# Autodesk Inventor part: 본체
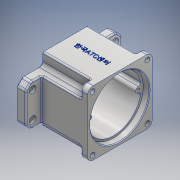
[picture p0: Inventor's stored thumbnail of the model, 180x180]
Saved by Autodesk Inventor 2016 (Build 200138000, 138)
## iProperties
Created: 2017-01
Part Number: 본체
Material: 알루미늄 6061
Document SubType Name: Modeling
Designer: Owner
Density: 2.7 g/cm^3
Appearance: 알루미늄 - 평지
Mass: 877.754 g
Surface Area: 763.669 cm^2
Volume: 325.094 cm^3
Author: Owner
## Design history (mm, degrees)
sketch "스케치4"
  geometry: L1 (70, -30)-(70, 30); L2 (-70, -30)-(-70, 30); L3 (-33, -47)-(33, -47); L4 (33, 47)-(-33, 47); L5 (70, 30)-(33, 30); L6 (-33, -30)-(-70, -30); L7 (-33, 47)-(-33, 30); L8 (-33, -30)-(-33, -47); L9 (-70, 30)-(-33, 30); L10 (33, -30)-(70, -30); L11 (33, -47)-(33, -30); L12 (33, 30)-(33, 47); 5 further points
  constraints: 24 end point, 10 equal length, 4 midpoint, 4 perpendicular, 3 horizontal, 2 collinear, 2 horizontal alignment, 2 vertical alignment
  dimensions: "d6" = 66 distance of L4.start L4.end; "d7" = 60 distance of L1.start L1.end; "d8" = 60 distance of L2.start L2.end; "d9" = 66 distance of L3.start L3.end; "d10" = 94 distance between parallel lines of L3 L4; "d11" = 140 distance between parallel lines of L1 L2
extrude "돌출2" new body sketch "스케치4" distance "d12" = 13; taper "d13" = 0 deg
sketch "스케치6"
  geometry: L1 (-33, 47)-(33, 47); L2 (33, 47)-(33, -47); L3 (33, -47)-(-33, -47); L4 (-33, -47)-(-33, 47); L5 (-33, 47)-(33, -47); L6 (33, 47)-(-33, -47); 1 further point
  constraints: 12 end point, 2 midpoint, 2 parallel, 1 horizontal, 1 perpendicular
extrude "돌출3" join sketch "스케치6" distance "d16" = 80; taper "d17" = 0 deg
sketch "스케치7"
  geometry: C1 r 27.5 at (11, 0); 2 further points
  constraints: 1 centre point, 1 coincident, 1 horizontal alignment
  dimensions: "d18" = 11 distance of point (11, 0) point (0, 0); "d19" = 55 diameter of C1
extrude "돌출4" join sketch "스케치7" distance "d20" = 7; taper "d21" = 0 deg
hole "구멍1" diameter "d24" = 32; stored, may be unused: countersink angle "d28" = 90 deg, drill point angle "d30" = 0 deg; dims "d25" = 6, "d26" = 4, "d27" = 2, "d29" = 8, "d31" = 10, "d32" = 10
hole "구멍2" diameter "d35" = 25; stored, may be unused: countersink angle "d39" = 90 deg, drill point angle "d41" = 0 deg; dims "d36" = 6, "d37" = 4, "d38" = 2, "d40" = 5, "d42" = 10, "d43" = 10
sketch "스케치8"
  geometry: L1 (-47, -47)-(47, -47); L2 (47, -47)-(47, 47); L3 (47, 47)-(-47, 47); L4 (-47, 47)-(-47, -47); L5 (-47, -47)-(47, 47); L6 (47, -47)-(-47, 47); 1 further point
  constraints: 12 end point, 2 midpoint, 2 parallel, 1 horizontal, 1 perpendicular
  dimensions: "d44" = 94 distance of L3.end L1.start; "d45" = 94 distance of L2.end L3.end
extrude "돌출5" join sketch "스케치8" distance "d46" = 10; taper "d47" = 0 deg
sketch "스케치9"
  geometry: L1 (30, 33)-(30, 70) reference; L2 (-30, -47)-(30, -47); L3 (30, -47)-(30, 47); L4 (30, 47)-(-30, 47); L5 (-30, 47)-(-30, -47); L6 (-30, -47)-(30, 47); L7 (30, -47)-(-30, 47); 1 further point
  constraints: 12 end point, 2 midpoint, 2 parallel, 1 horizontal, 1 perpendicular, 1 point on line
  dimensions: "d48" = 94 distance of L4.end L2.start
extrude "돌출6" join sketch "스케치9" stored distance "d49" = 10; taper "d50" = 0 deg
sketch "스케치10"
  geometry: 2 further points
  constraints: 1 coincident
hole "구멍3" sketch "스케치10" at (0, 0) diameter "d51" = 80; stored, may be unused: countersink angle "d55" = 90 deg, drill point angle "d57" = 0 deg; dims "d52" = 6, "d53" = 4, "d54" = 2, "d56" = 71
sketch "스케치11"
  geometry: A1 r 21 centre (-11, 0) between (7.984, 8.978) and (7.984, -8.978); A2 r 15 centre (20, 0) between (7.984, -8.978) and (7.984, 8.978); 3 further points
  constraints: 4 point on circle, 2 centre point, 2 coincident, 1 horizontal alignment
  dimensions: "d58" = 42 diameter of A1; "d71" = 20 distance of point (20, 0) point (0, 0); "d72" = 30 diameter of A2
extrude "돌출7" join sketch "스케치11" distance "d59" = 7; taper "d60" = 0 deg
hole "구멍4" diameter "d63" = 35; stored, may be unused: countersink angle "d67" = 90 deg, drill point angle "d69" = 0 deg; dims "d61" = 10, "d62" = 10, "d64" = 6, "d65" = 4, "d66" = 2, "d68" = 10
fillet "모깎기1" dims "d70" = 0.3
hole "구멍5" diameter "d75" = 22; stored, may be unused: countersink angle "d79" = 90 deg, drill point angle "d81" = 0 deg; dims "d73" = 10, "d74" = 10, "d76" = 6, "d77" = 4, "d78" = 2, "d80" = 7
hole "구멍6" diameter "d84" = 19; stored, may be unused: countersink angle "d88" = 90 deg, drill point angle "d90" = 0 deg; dims "d82" = 10, "d83" = 10, "d85" = 6, "d86" = 4, "d87" = 2, "d89" = 1
fillet "모깎기2" dims "d91" = 0.3
fillet "모깎기3" dims "d92" = 2
hole "구멍7" diameter "d95" = 86; stored, may be unused: countersink angle "d99" = 90 deg, drill point angle "d101" = 0 deg; dims "d93" = 10, "d94" = 10, "d96" = 6, "d97" = 4, "d98" = 2, "d100" = 9
fillet "모깎기4" dims "d102" = 0.3
chamfer "모따기1" distance "d103" = 1; stored, may be unused: second distance "d104" = 2, angle "d105" = 45 deg
sketch "스케치12"
  geometry: C1 r 43 at (0, 0); A1 r 36 centre (0, 0) between (0, 36) and (0, -36); A2 r 4 centre (0, 36) between (-3.997, 35.852) and (3.997, 35.852); A3 r 4 centre (0, -36) between (3.997, -35.852) and (-3.997, -35.852); A4 r 3.5 centre (-7.495, 35.722) between (-3.995, 35.778) and (-8.214, 39.148); A5 r 3.5 centre (7.495, 35.722) between (8.214, 39.148) and (3.995, 35.778); A6 r 3.5 centre (7.495, -35.722) between (3.995, -35.778) and (8.214, -39.148); A7 r 40 centre (0, 0) between (-8.214, 39.148) and (-8.214, -39.148); A8 r 40 centre (0, 0) between (8.214, -39.148) and (8.214, 39.148); A9 r 3.5 centre (-7.495, -35.722) between (-8.214, -39.148) and (-3.995, -35.778); 1 further point
  constraints: 26 point on circle, 10 centre point, 5 tangent, 4 vertical alignment, 3 coincident, 1 horizontal alignment
  dimensions: "d106" = 72 diameter of A1; "d107" = 8 diameter of A2; "d108" = 8 diameter of A3; "d111" = 3.5 radius of A4; "d112" = 3.5 radius of A5; "d113" = 3.5 radius of A6; "d114" = 7 diameter of A9; "d115" = 40 radius of A7; "d116" = 40 radius of A8; "d117" = 86 diameter of C1
extrude "돌출8" join sketch "스케치12" distance "d118" = 62; taper "d119" = 0 deg
sketch "스케치13"
  geometry: 2 further points
  dimensions: "d120" = 60 vertical distance of point (0, 0) point (-19, -60); "d121" = 19 horizontal distance of point (0, 0) point (-19, -60)
hole "구멍8" sketch "스케치13" at (-19, -60) diameter "d122" = 4; stored, may be unused: countersink angle "d126" = 90 deg, drill point angle "d128" = 0 deg; dims "d123" = 6, "d124" = 4, "d125" = 2, "d127" = 9
hole "구멍9" diameter "d131" = 10; stored, may be unused: countersink angle "d135" = 90 deg, drill point angle "d137" = 0 deg; dims "d132" = 6, "d133" = 4, "d134" = 2, "d136" = 4, "d138" = 10, "d139" = 10
fillet "모깎기5" dims "d140" = 8
chamfer "모따기2" distance "d141" = 8; stored, may be unused: second distance "d142" = 2, angle "d143" = 45 deg
fillet "모깎기6" dims "d144" = 5
chamfer "모따기3" distance "d145" = 1; stored, may be unused: second distance "d146" = 2, angle "d147" = 45 deg
fillet "모깎기7" dims "d148" = 5
hole "구멍10" diameter "d151" = 3.242; stored, may be unused: countersink angle "d155" = 90 deg, drill point angle "d157" = 118 deg; dims "d152" = 7, "d153" = 4, "d154" = 2, "d156" = 9, "d189" = 10, "d190" = 10
sketch "스케치14"
  geometry: 2 further points
  dimensions: "d160" = 40 horizontal distance of point (0, 0) point (-40, 40); "d161" = 40 horizontal distance of point (0, 0) point (-40, 40)
hole "구멍11" sketch "스케치14" at (-40, 40) diameter "d162" = 7; stored, may be unused: countersink angle "d166" = 90 deg, drill point angle "d168" = 0 deg; dims "d163" = 8, "d164" = 4, "d165" = 2, "d167" = 9
fillet "모깎기8" dims "d172" = 2
fillet "모깎기9" dims "d173" = 3
fillet "모깎기10" dims "d174" = 2
fillet "모깎기11" dims "d175" = 2
fillet "모깎기12" dims "d176" = 2
fillet "모깎기13" dims "d177" = 2
fillet "모깎기14" dims "d178" = 2
fillet "모깎기15" dims "d179" = 2
sketch "스케치15"
  geometry: L1 (-80, 70)-(-80, 8) reference; L2 (0, 78)-(0, 0) reference; 3 further points
  constraints: 1 horizontal alignment, 1 midpoint, 1 other
  dimensions: "d180" = 40 distance from line of L2 point (-40, 39)
feature "엠보싱1" sketch "스케치15" dims "d181" = 0.5, "d182" = 0
sketch "스케치16"
  geometry: L1 (35, 33)-(45, 33) reference; L2 (30, 59.929)-(30, 38) reference; L3 (23.464, 68.536)-(28.536, 63.464) reference; L4 (-19.929, 70)-(19.929, 70) reference; L5 (-28.536, 63.464)-(-23.464, 68.536) reference; L6 (-30, 38)-(-30, 59.929) reference; L7 (-45, 33)-(-35, 33) reference; L8 (-47, -31)-(-47, 31) reference; L9 (-35, -33)-(-45, -33) reference; L10 (-30, -59.929)-(-30, -38) reference; L11 (-23.464, -68.536)-(-28.536, -63.464) reference; L12 (19.929, -70)-(-19.929, -70) reference; L13 (28.536, -63.464)-(23.464, -68.536) reference; L14 (30, -38)-(30, -59.929) reference; L15 (45, -33)-(35, -33) reference; L16 (47, 31)-(47, -31) reference; L17 (45, -32)-(35, -32); L18 (29, -38)-(29, -59.929); L19 (27.828, -62.757)-(22.757, -67.828); L20 (19.929, -69)-(-19.929, -69); L21 (-22.757, -67.828)-(-27.828, -62.757); L22 (-29, -59.929)-(-29, -38); L23 (-35, -32)-(-45, -32); L24 (-46, -31)-(-46, 31); L25 (-45, 32)-(-35, 32); L26 (-29, 38)-(-29, 59.929); L27 (-27.828, 62.757)-(-22.757, 67.828); L28 (-19.929, 69)-(19.929, 69); L29 (22.757, 67.828)-(27.828, 62.757); L30 (29, 59.929)-(29, 38); L31 (35, 32)-(45, 32); L32 (46, 31)-(46, -31); L33 (45, -33)-(35, -33); L34 (30, -38)-(30, -59.929); L35 (28.536, -63.464)-(23.464, -68.536); L36 (19.929, -70)-(-19.929, -70); L37 (-23.464, -68.536)-(-28.536, -63.464); L38 (-30, -59.929)-(-30, -38); L39 (-35, -33)-(-45, -33); L40 (-47, -31)-(-47, 31); L41 (-45, 33)-(-35, 33); L42 (-30, 38)-(-30, 59.929); L43 (-28.536, 63.464)-(-23.464, 68.536); L44 (-19.929, 70)-(19.929, 70); L45 (23.464, 68.536)-(28.536, 63.464); L46 (30, 59.929)-(30, 38); L47 (35, 33)-(45, 33); L48 (47, 31)-(47, -31); C1 r 2 at (-19, 60) reference; C2 r 2 at (-19, -60) reference; C3 r 2 at (19, 60) reference; C4 r 2 at (19, -60) reference; C5 r 27.8 at (11, 0) reference; A1 r 2 centre (45, 31) between (47, 31) and (45, 33) reference; A2 r 5 centre (35, 38) between (30, 38) and (35, 33) reference; A3 r 5 centre (25, 59.929) between (30, 59.929) and (28.536, 63.464) reference; A4 r 5 centre (19.929, 65) between (23.464, 68.536) and (19.929, 70) reference; A5 r 5 centre (-19.929, 65) between (-19.929, 70) and (-23.464, 68.536) reference; A6 r 5 centre (-25, 59.929) between (-28.536, 63.464) and (-30, 59.929) reference; A7 r 5 centre (-35, 38) between (-35, 33) and (-30, 38) reference; A8 r 2 centre (-45, 31) between (-45, 33) and (-47, 31) reference; A9 r 2 centre (-45, -31) between (-47, -31) and (-45, -33) reference; A10 r 5 centre (-35, -38) between (-30, -38) and (-35, -33) reference; A11 r 5 centre (-25, -59.929) between (-30, -59.929) and (-28.536, -63.464) reference; A12 r 5 centre (-19.929, -65) between (-23.464, -68.536) and (-19.929, -70) reference; A13 r 5 centre (19.929, -65) between (19.929, -70) and (23.464, -68.536) reference; A14 r 5 centre (25, -59.929) between (28.536, -63.464) and (30, -59.929) reference; A15 r 5 centre (35, -38) between (35, -33) and (30, -38) reference; A16 r 2 centre (45, -31) between (45, -33) and (47, -31) reference; A17 r 1 centre (45, -31) between (45, -32) and (46, -31); A18 r 6 centre (35, -38) between (35, -32) and (29, -38); A19 r 4 centre (25, -59.929) between (27.828, -62.757) and (29, -59.929); A20 r 4 centre (19.929, -65) between (19.929, -69) and (22.757, -67.828); A21 r 4 centre (-19.929, -65) between (-22.757, -67.828) and (-19.929, -69); A22 r 4 centre (-25, -59.929) between (-29, -59.929) and (-27.828, -62.757); A23 r 6 centre (-35, -38) between (-29, -38) and (-35, -32); A24 r 1 centre (-45, -31) between (-46, -31) and (-45, -32); A25 r 1 centre (-45, 31) between (-45, 32) and (-46, 31); A26 r 6 centre (-35, 38) between (-35, 32) and (-29, 38); A27 r 4 centre (-25, 59.929) between (-27.828, 62.757) and (-29, 59.929); A28 r 4 centre (-19.929, 65) between (-19.929, 69) and (-22.757, 67.828); A29 r 4 centre (19.929, 65) between (22.757, 67.828) and (19.929, 69); A30 r 4 centre (25, 59.929) between (29, 59.929) and (27.828, 62.757); A31 r 6 centre (35, 38) between (29, 38) and (35, 32); A32 r 1 centre (45, 31) between (46, 31) and (45, 32); A33 r 2 centre (45, -31) between (45, -33) and (47, -31); A34 r 5 centre (35, -38) between (35, -33) and (30, -38); A35 r 5 centre (25, -59.929) between (28.536, -63.464) and (30, -59.929); A36 r 5 centre (19.929, -65) between (19.929, -70) and (23.464, -68.536); A37 r 5 centre (-19.929, -65) between (-23.464, -68.536) and (-19.929, -70); A38 r 5 centre (-25, -59.929) between (-30, -59.929) and (-28.536, -63.464); A39 r 5 centre (-35, -38) between (-30, -38) and (-35, -33); A40 r 2 centre (-45, -31) between (-47, -31) and (-45, -33); A41 r 2 centre (-45, 31) between (-45, 33) and (-47, 31); A42 r 5 centre (-35, 38) between (-35, 33) and (-30, 38); A43 r 5 centre (-25, 59.929) between (-28.536, 63.464) and (-30, 59.929); A44 r 5 centre (-19.929, 65) between (-19.929, 70) and (-23.464, 68.536); A45 r 5 centre (19.929, 65) between (23.464, 68.536) and (19.929, 70); A46 r 5 centre (25, 59.929) between (30, 59.929) and (28.536, 63.464); A47 r 5 centre (35, 38) between (30, 38) and (35, 33); A48 r 2 centre (45, 31) between (47, 31) and (45, 33); 1 further point
  constraints: 64 end point, 64 point on circle, 32 centre point, 62 other
  dimensions: "d183" = 1 distance between parallel lines of L16 L32; "d184" = 1 distance between parallel lines of L32 L48
extrude "돌출9" cut sketch "스케치16" distance "d185" = 1; taper "d186" = 0 deg
node "솔리드2"
mirror "대칭1"
mirror "대칭2"
mirror "대칭3"
pattern_circular "원형 패턴1" dims angle "d170" = 360 deg
node "투영된 루프1"
